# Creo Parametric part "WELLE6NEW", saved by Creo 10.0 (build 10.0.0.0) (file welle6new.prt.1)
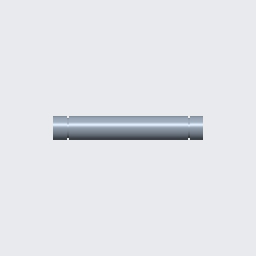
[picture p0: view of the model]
Units: millimeter Newton Second (mmNs); MM, TONNE, SECS

Created from: XX_INLBS_PART_SOLID_ABS.PRT

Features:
  1. datum plane "RIGHT"
  2. datum plane "TOP"
  3. datum plane "FRONT"
  4. coordinate system
  5. extrusion "Profil 1"
  6. datum plane "DTM1"
  7. sketch "Skizze 1"
  8. sketch "Skizze 2"
  9. sketch "Skizze 3"
  10. sketch "Skizze 4"
  11. sketch "Skizze 5"
  12. sketch "Skizze 6"
  13. revolved cut "Drehen 1"
  14. sketch "Skizze 7"
  15. revolved cut "Drehen 2"

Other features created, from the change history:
  extrusion "Profil 2"
  curve "Schneiden 1"
  sketch "Skizze 1" (4 times)
  revolved cut "Drehen 1" (2 times)
  feature "Drehen 1"
  revolved cut "Drehen 2"

Surfaces: 6 plane, 5 cylinder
